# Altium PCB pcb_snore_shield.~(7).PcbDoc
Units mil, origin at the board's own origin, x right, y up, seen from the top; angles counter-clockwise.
Board outline 6000 x 4000 mil, 2 copper layers (Top Layer, Bottom Layer); 51 components, 37 nets, 162 pads, 0 vias.
Unrouted connection lines stored in the file: 100.
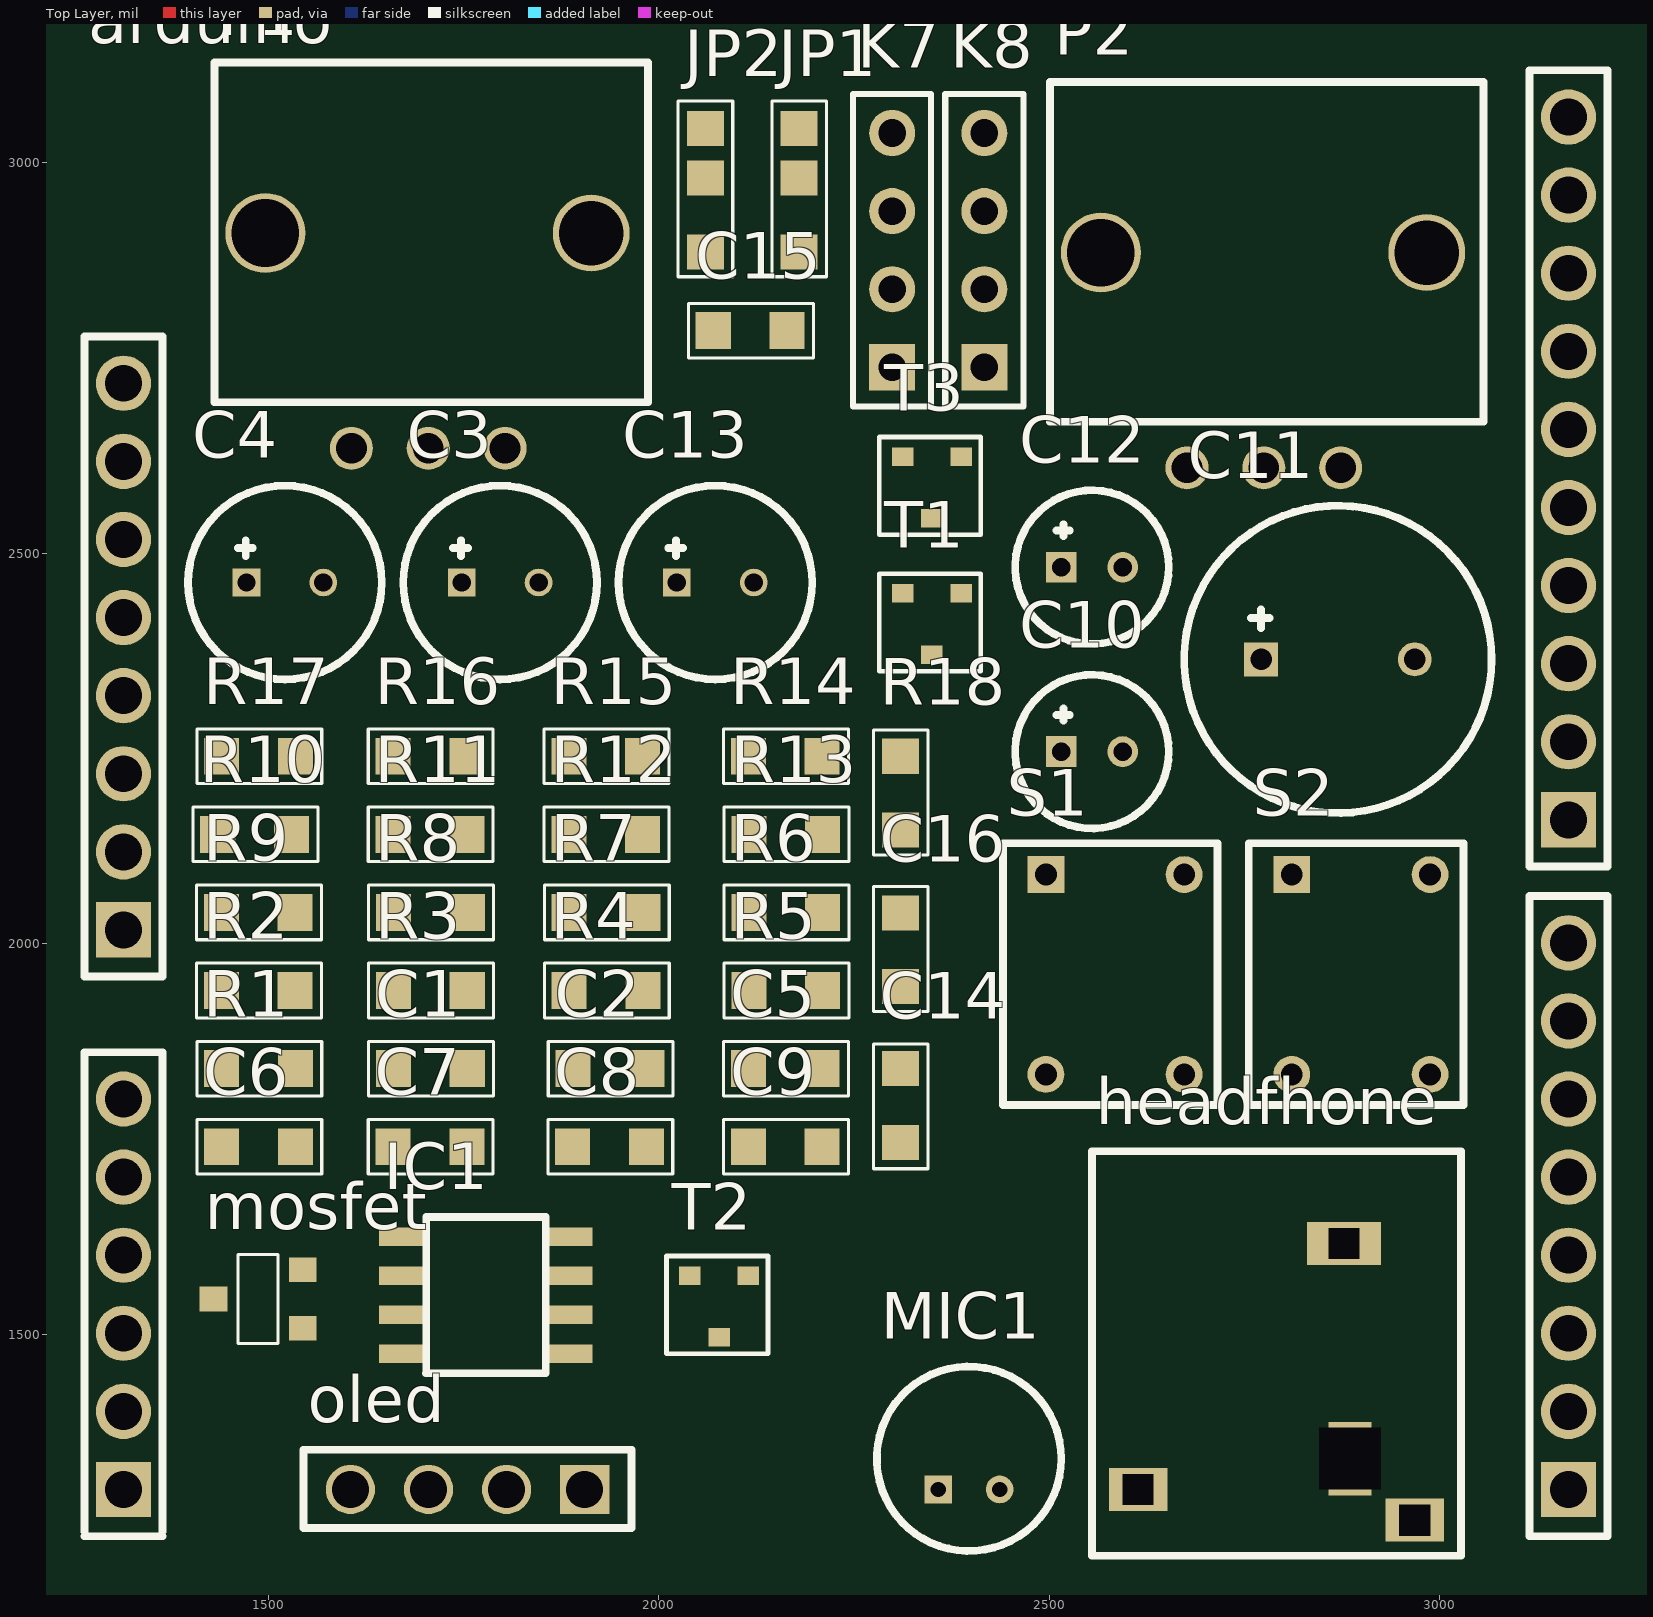
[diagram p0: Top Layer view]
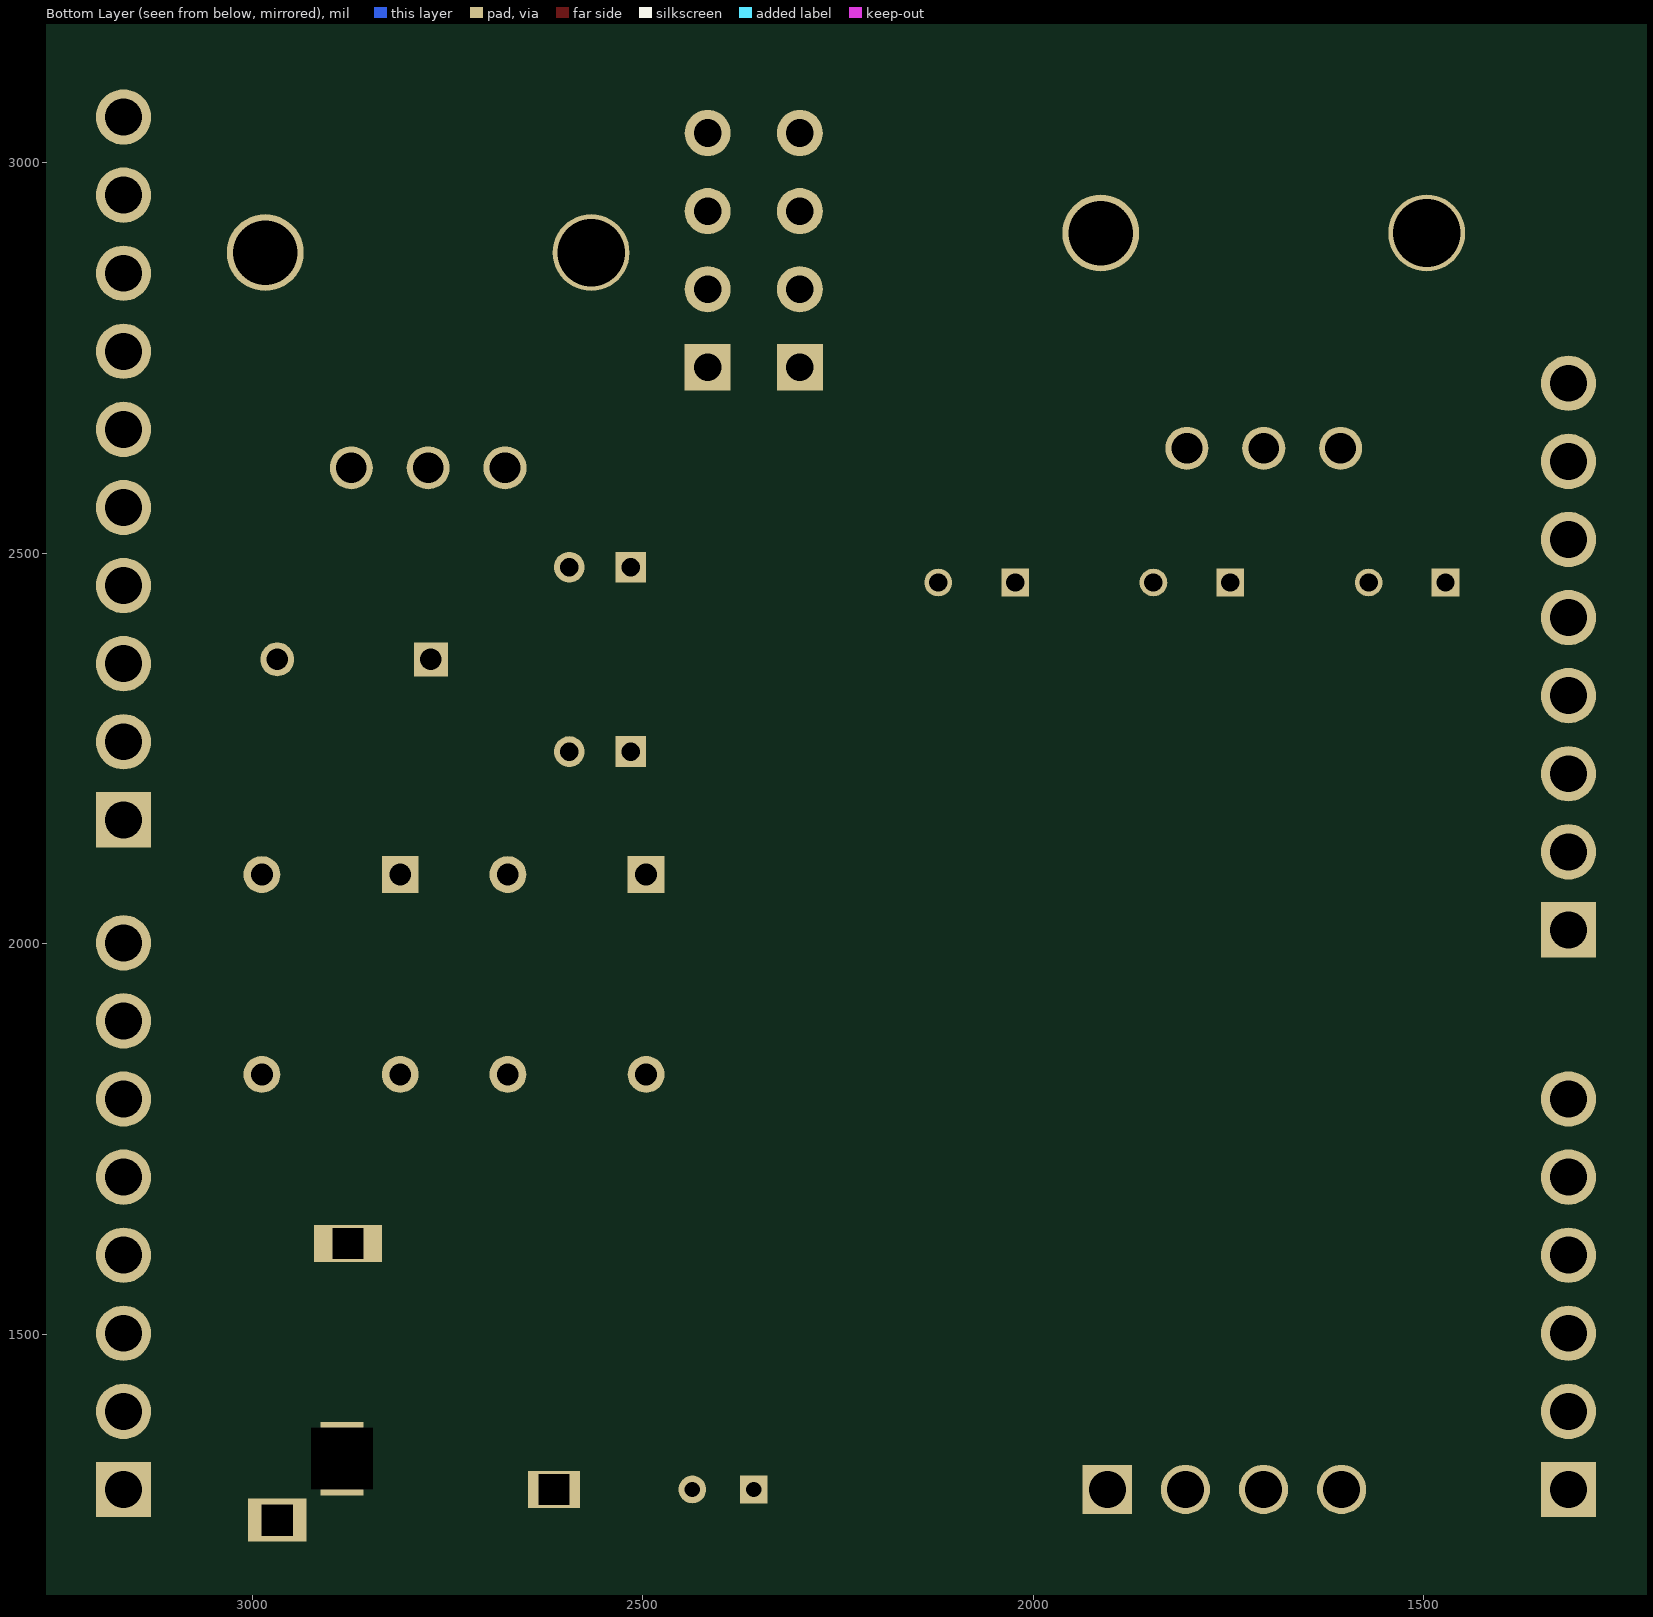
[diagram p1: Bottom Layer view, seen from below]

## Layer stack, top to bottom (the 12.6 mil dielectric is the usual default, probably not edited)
Top Solder: solder mask 0.4, Solder Resist, Dk 3.5
Top Layer: signal copper 1.4
Dielectric 1: dielectric 12.6, FR-4, Dk 4.8
Bottom Layer: signal copper 1.4
Bottom Solder: solder mask 0.4, Solder Resist, Dk 3.5

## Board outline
1000,1000 7000,1000 7000,5000 1000,5000

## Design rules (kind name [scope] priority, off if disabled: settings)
Clearance [All] p1: gap=10 ignorepadtopadclearanceinfootprint=FALSE except(0: Arc-Hole Track-Hole SMDPad-Hole THPad-Hole Via-Hole Fill-Hole Poly-Hole Region-Hole Text-Hole)
PolygonConnect [All] p1: connectstyle=Relief reliefconductorwidth=10 reliefentries=4 polygonreliefangle="90 Angle" airgapwidth=10
RoomDefinition snor_shield_sheet [InComponentClass('snor_shield_sheet')] p1: confinementstyle=ConfineIn formatcopy=TRUE lockcomponents=FALSE outline 7178.7,2815 20768.7,2815 20768.7,5240 7178.7,5240
RoutingVias [All] p1: holewidth=28 width=50 viastyle="Through Hole" minholewidth=28 minwidth=50 maxholewidth=28 maxwidth=50
SolderMaskExpansion [All] p1: expansion=4 istentingtop=FALSE
Width [All] p1: maxlimit=10 minlimit=10 preferedwidth=10
30 further rules are at their usual default settings.

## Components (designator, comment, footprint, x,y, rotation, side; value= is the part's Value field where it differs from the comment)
arduino "arduino r3 shield" arduino 1314.8,1301.1 r0 top
C1 "Capitor" "SMD 0805" 1648.7,1840 r0 top value=1µF
C2 "Capitor" "SMD 0805" 1878.7,1840 r0 top value=100nF
C3 "Cap Pol1" "elektor trans 2" 1747.87,2462.52 r0 top value=47µF/16V
C4 "Cap Pol1" "elektor trans 2" 1472.28,2462.52 r0 top value=47µF/16V
C5 "Capitor" "SMD 0805" 2103.19,1840 r0 top value=100pF
C6 "Capitor" "SMD 0805" 1428.7,1740 r0 top value=100pF
C7 "Capitor" "SMD 0805" 1648.19,1740 r0 top value=1nF
C8 "Capitor" "SMD 0805" 1878.19,1740 r0 top value=1µF
C9 "Capitor" "SMD 0805" 2103.19,1740 r0 top value=47nF
C10 "Cap Pol1" "elecktor trans 1" 2515.59,2245.98 r0 top value=10µF/16V
C11 "Cap Pol1" "elektor trans 3" 2771.5,2364.09 r0 top value=220µF/16V
C12 "Cap Pol1" "elecktor trans 1" 2515.59,2482.2 r0 top value=10µF/16V
C13 "Cap Pol1" "elektor trans 2" 2023.46,2462.52 r0 top value=47µF/16V
C14 "Cap" "SMD 0805" 2310,1851.81 r270 top value=100nF
C15 "Capitor" "SMD 0805" 2058.19,2785 r0 top value=100nF
C16 "Capitor" "SMD 0805" 2310,1933.19 r90 top value=100nF
headfhone "K-JACK-STEREO-3.5MM" adioplug3.5mm 2614.02,1301.1 r0 top
IC1 "LM386M-1/NOPB" LM386M-1/NOPB 1672.4,1625 r0 top
JP1 "Res2" soldeer_jumper 2180,2874.02 r90 top value=0Ohm
JP2 "Res2" soldeer_jumper 2060,2874.02 r90 top value=0Ohm
K7 "Header 4" HDR1X4 2299.06,2738.11 r90 top
K8 "Header 4" HDR1X4 2417.17,2738.11 r90 top (schematic designator K6)
MIC1 "Mic2" "Electret Condenser Microphone" 2358.11,1301.1 r0 top
mosfet "power MOSFET" "power mosfet" 1430,1545 r90 top
oled "1X4 socked" "oled scherm" 1905.35,1301.1 r180 top
P1 "Res Adj2" potmeter 1496.38,2910 r0 top value=100k
P2 "Res Adj2" potmeter 2566.38,2885 r0 top value=10K
R1 "weerstand" "SMD 0805" 1428.7,1840 r0 top value=27K
R2 "weerstand" "SMD 0805" 1428.19,1940 r0 top value=15K
R3 "weerstand" "SMD 0805" 1648.7,1940 r0 top value=27K
R4 "weerstand" "SMD 0805" 1873.7,1940 r0 top value=1K2
R5 "weerstand" "SMD 0805" 2103.7,1940 r0 top value=10K
R6 "weerstand" "SMD 0805" 2103.7,2040 r0 top value=680Ohm
R7 "weerstand" "SMD 0805" 1873.7,2040 r0 top value=10K
R8 "weerstand" "SMD 0805" 1648.7,2040 r0 top value=10K
R9 "weerstand" "SMD 0805" 1428.19,2040 r0 top value=10K
R10 "weerstand" "SMD 0805" 1423.7,2140 r0 top value=180K
R11 "weerstand" "SMD 0805" 1648.19,2140 r0 top value=180K
R12 "weerstand" "SMD 0805" 1873.19,2140 r0 top value=10K
R13 "weerstand" "SMD 0805" 2103.7,2140 r0 top value=1K
R14 "weerstand" "SMD 0805" 2103.19,2240 r0 top value=100K
R15 "weerstand" "SMD 0805" 1873.19,2240 r0 top value=10Ohm
R16 "weerstand" "SMD 0805" 1648.19,2240 r0 top value=1K
R17 "Res2" "SMD 0805" 1428.7,2240 r0 top value=100K
R18 "weerstand" "SMD 0805" 2310,2133.7 r90 top value=10Ohm
S1 "SW-PB" switch 2495.91,2088.5 r0 top
S2 "SW-PB" switch 2810.87,2088.5 r0 top
T1 "BC847C" "bipolar BjT" 2312.6,2448.74 r0 top
T2 "BC847C" "bipolar BjT" 2040.2,1575 r0 top
T3 "BC847C" "bipolar BjT" 2312.6,2623.74 r0 top

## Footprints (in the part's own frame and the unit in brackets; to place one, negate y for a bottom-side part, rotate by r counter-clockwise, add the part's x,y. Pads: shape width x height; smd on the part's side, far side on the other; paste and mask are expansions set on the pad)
adioplug3.5mm [mm]
  rect 1.4x2.4 hole 2 square: B(6.9,1)
  rect 1.9x1.4 hole 1 square: R(9,-1)
  rect 2.4x1.4 / inner rect 2.2x1.27 / far side rect 2.2x1.2 hole 1 square: S(6.7,8)
  rect 1.9x1.4 / inner rect 2.54x1.27 / far side rect 1.7x1.2 hole 1 square: T(0,0)
  silkscreen extent -1.5,-2.16 10.5,11
arduino [mm]
  round 1.8 hole 1.2: 3.3V(0,28.36) 5V(0,25.82) 14(0,35.98) A0/PC0(0,12.7) A1/PC1(0,10.16) A2/PC2(0,7.62) A3/PC3(0,5.08) A4/PC4(0,2.54) A4/PC4(47,42.1) A5/PC5(47,44.64) AREF(47,39.56) GND(0,20.74) GND(0,23.28) GND(47,37.02) INT0/PD2(47,5.08) INT1/PD3(47,7.62) IOREF(0,33.44) MISO/PB4(47,31.94) MOSI/PB3(47,29.4) PB1(47,24.32) PD4(47,10.16) PD5(47,12.7) PD6(47,15.24) PD7(47,17.78) RST/PC6(0,30.9) SCK/PB5(47,34.48) SS/PB2(47,26.86) TX/PD1(47,2.54)
  rect 1.8x1.8 hole 1.2: A5/PC5(0,0) PB0(47,21.78) RX/PD0(47,0) VIN(0,18.2)
  silkscreen extent -1.27,-1.52 48.27,46.16
"bipolar BjT" [mm]
  rect 0.7x0.6 smd: 1(1.9,0) 2(0,0) 3(0.95,-2)
  silkscreen extent -0.76,-2.54 2.54,0.64
"elecktor trans 1" [mm]
  rect 1x1 hole 0.6: 1(0,0)
  round 1 hole 0.6: 2(2,0)
  silkscreen extent -1.5,-2.5 3.5,2.5
"Electret Condenser Microphone" [mm]
  rect 0.9x0.9 hole 0.5: 1(0,0)
  round 0.9 hole 0.5: 2(2,0)
  silkscreen extent -2,-2 4,4
"elektor trans 2" [mm]
  rect 0.9x0.9 hole 0.6: 1(0,0)
  round 0.9 hole 0.6: 2(2.5,0)
  silkscreen extent -1.9,-3.15 4.4,3.15
"elektor trans 3" [mm]
  rect 1.1x1.1 hole 0.7: 1(0,0)
  round 1.1 hole 0.7: 2(5,0)
  silkscreen extent -2.5,-5 7.5,5
HDR1X4 [mm] "Connector; Header; 4 Position"
  rect 1.5x1.5 hole 0.9: 1(0,0)
  round 1.5 hole 0.9: 2(2.54,0) 3(5.08,0) 4(7.62,0)
  silkscreen extent -1.27,-1.27 8.89,1.27
LM386M-1/NOPB [mm]
  rect 1.55x0.6 smd: 1(0,0) 2(0,-1.27) 3(0,-2.54) 4(0,-3.81) 5(5.4,-3.81) 6(5.4,-2.54) 7(5.4,-1.27) 8(5.4,0)
  silkscreen extent 0.75,-4.44 4.65,0.64
"oled scherm" [mm]
  rect 1.6x1.6 hole 1.2: 1(0,0)
  round 1.6 hole 1.2: 2(5.08,0) 3(7.62,0) 4(2.54,0)
  silkscreen extent -1.52,-1.29 9.14,1.25
potmeter [mm]
  round 1.4 hole 1: 1(2.8,-7) 2(5.3,-7)
  round 1.4 / inner oval 1.4x0.064 / far side round 1.4 hole 1: 3(7.8,-7)
  round 2.5 / inner oval 2.5x0.064 / far side round 2.5 hole 2.1: 4(10.6,0)
  round 2.6 / inner round 2.5 / far side round 2.5 hole 2.2: 5(0,0)
  silkscreen extent -1.65,-5.5 12.45,5.55
"power mosfet" [mm]
  rect 0.8x0.9 smd: 1(-0.95,-2.9) 2(0.95,-2.9) 3(0,0)
  silkscreen extent -1.45,-2.1 1.45,-0.8
"SMD 0805" [mm]
  rect 1.14x1.2 smd: 1(0.3,0) 2(2.7,0)
  silkscreen extent -0.51,-0.89 3.56,0.89
soldeer_jumper [mm]
  rect 1.14x1.2 smd: 1(0.3,0) 2(2.7,0) 3(4.318,0)
  silkscreen extent -0.51,-0.89 5.21,0.89
switch [mm]
  rect 1.2x1.2 hole 0.71: 1(0,0)
  round 1.2 hole 0.71: 2(0,-6.5) 3(4.5,-6.5) 4(4.5,0)
  silkscreen extent -1.4,-7.49 5.59,1.02

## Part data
C1 C2 C5 C6 C7 C8 C9 C15 C16: "Capacitor"
C3 C4 C13: library part "Cap Pol1_1", "Polarized Capacitor (Radial) 47µF"
C10 C12: "Polarized Capacitor (Radial) 10µF"
C11: library part "Cap Pol1_2", "Polarized Capacitor (Radial) 220µF"
C14: library part Capitor, "Capacitor"
JP1 JP2: library part solderjump, "Resistor"
K7: "Header, 4-Pin,2mm"
K8: "Header, 4-Pin"
MIC1: "Microphone"
P1: "Variable Resistor 10K"
P2: library part "Res Adj2_1", "Variable Resistor"
R1 R2 R3 R4 R5 R6 R7 R8 R9 R10 R11 R12 R13 R14 R15 R16 R18: "Resistor"
R17: library part weerstand, "Resistor"
S1 S2: library part switch, "Switch"
T1 T2 T3: library part BJT, "NPN General Purpose Amplifier"

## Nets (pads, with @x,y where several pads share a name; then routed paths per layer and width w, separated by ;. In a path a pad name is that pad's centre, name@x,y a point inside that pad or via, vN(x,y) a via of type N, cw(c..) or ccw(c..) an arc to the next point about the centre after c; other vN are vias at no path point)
+5V: C13.1 C14.2 IC1.6 R1.2 R3.2 R5.2 R18.2
GND: arduino.GND C2.1 C3.2 C4.2 C5.1 C12.2 C13.2 C14.1 C15.1 C16.1 headfhone.S IC1.2 IC1.4 JP1.3 JP2.3 K7.1 K8.4 MIC1.2 mosfet.2 P2.1 R2.1 R4.1 R12.1 R14.1 R15.1 S1.1 S2.1 T2.3
Netarduino_A0/PC0: arduino.A0/PC0 R3.1 T1.2
Netarduino_A4/PC4: arduino.A4/PC4 oled.4
Netarduino_A5/PC5: arduino.A5/PC5 oled.3
Netarduino_INT0/PD2: arduino.INT0/PD2 K7.4 K8.1
Netarduino_INT1/PD3: arduino.INT1/PD3 K7.3 K8.2
Netarduino_IOREF: arduino.IOREF C15.2 JP1.1 JP2.1 K7.2 K8.3 R18.1
Netarduino_PB0: arduino.PB0 mosfet.3 P1.1 R8.1
Netarduino_PB1: arduino.PB1 mosfet.1 R14.2
Netarduino_PD5: arduino.PD5 S1.2
Netarduino_PD6: arduino.PD6 R7.1
Netarduino_PD7: arduino.PD7 S2.2
NetC1_1: C1.1 MIC1.1 R5.1
NetC1_2: C1.2 R6.1
NetC2_2: C2.2 R1.1 R2.2 R6.2 T1.1
NetC3_1: C3.1 R4.2 T1.3
NetC4_1: C4.1 C16.2 R7.2 R9.2 R13.2
NetC5_2: C5.2 R11.1 T3.1
NetC6_1: C6.1 C8.1 P1.3 R12.2 T3.3
NetC6_2: C6.2 C7.2 R10.1 R11.2
NetC7_1: C7.1 P1.2
NetC8_2: C8.2 R17.2
NetC9_1: C9.1 R15.2
NetC9_2: C9.2 C11.1 IC1.5
NetC10_1: C10.1 R16.2
NetC10_2: C10.2 IC1.8
NetC11_2: C11.2 headfhone.R headfhone.T
NetC12_1: C12.1 IC1.7
NetIC1_1: IC1.1 R16.1
NetIC1_3: IC1.3 P2.2
NetJP1_2: JP1.2 oled.1
NetJP2_2: JP2.2 oled.2
NetP2_3: P2.3 R17.1
NetR8_2: R8.2 T2.1
NetR9_1: R9.1 R10.2 T2.2
NetR13_1: R13.1 T3.2
pads on no net: arduino.3.3V arduino.5V arduino.14 arduino.A1/PC1 arduino.A2/PC2 arduino.A3/PC3 arduino.AREF arduino.MISO/PB4 arduino.MOSI/PB3 arduino.PD4 arduino.RST/PC6 arduino.RX/PD0 arduino.SCK/PB5 arduino.SS/PB2 arduino.TX/PD1 arduino.VIN headfhone.B P1.4 P1.5 P2.4 P2.5 S1.3 S1.4 S2.3 S2.4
